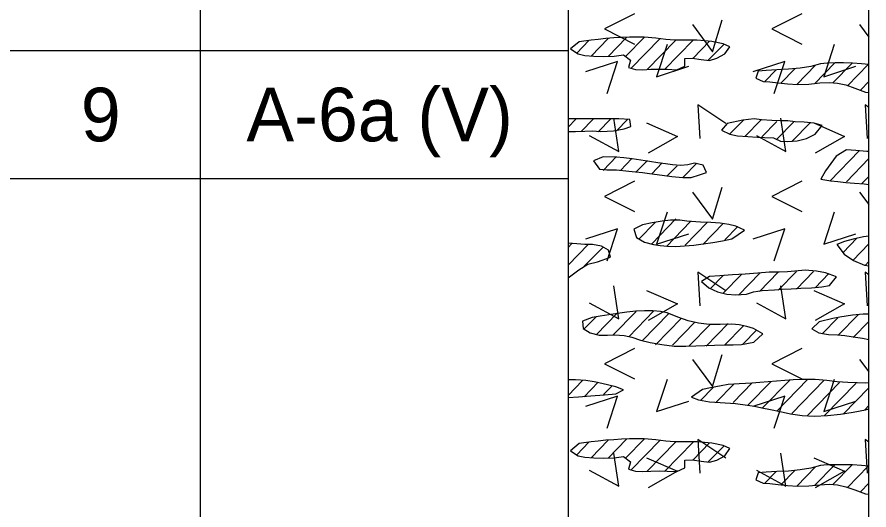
# Model space of a CAD drawing. Extents: x 0 to 0.83, y -0.65 to 1.27.
# Drawn here: x 0.7272 to 0.8333, y 0.4451 to 0.5064 of the extents above; entities that cross this region are included whole.
import ezdxf

# ---------------------------------------------------------------- set-up
doc = ezdxf.new("R2010")
doc.units = 0

msp = doc.modelspace()

# ---------------------------------------------------------------- linework, layer by layer
for points in [[(0, 0), (0.83333, 0), (0.83333, 1.275), (0, 1.275)], [(0, 0), (0.83333, 0), (0.83333, 1.275), (0, 1.275)], [(0, 0), (0.83333, 0), (0.83333, 1.275), (0, 1.275)], [(0, 0), (0.83333, 0), (0.83333, 1.275), (0, 1.275)], [(0, 0), (0.83333, 0), (0.83333, 1.275), (0, 1.275)], [(0.79708, 0.50181), (0.79794, 0.50163), (0.79904, 0.50152), (0.80028, 0.50149), (0.80156, 0.50154), (0.80274, 0.50169), (0.80361, 0.50103), (0.80338, 0.50014), (0.80422, 0.49987), (0.80517, 0.49985), (0.80613, 0.4999), (0.8072, 0.49993), (0.80818, 0.4999), (0.80939, 0.49983), (0.81037, 0.50029), (0.81038, 0.50124), (0.8113, 0.5013), (0.81244, 0.50112), (0.81346, 0.50101), (0.81438, 0.50127), (0.81539, 0.50181), (0.81601, 0.50272), (0.81517, 0.50309), (0.81374, 0.50337), (0.81285, 0.50346), (0.81187, 0.50352), (0.81, 0.50352), (0.8091, 0.50354), (0.808, 0.50362), (0.80678, 0.50377), (0.8053, 0.5039), (0.80443, 0.50392), (0.80349, 0.5039), (0.80251, 0.50386), (0.80152, 0.5038), (0.80054, 0.50372), (0.79959, 0.50363), (0.7987, 0.50353), (0.79722, 0.50331), (0.79614, 0.50243)], [(0.83241, 0.50059), (0.83129, 0.50066), (0.83017, 0.50069), (0.8291, 0.50069), (0.82811, 0.50066), (0.82728, 0.50057), (0.82608, 0.50027), (0.82476, 0.50004), (0.8233, 0.4999), (0.82183, 0.49982), (0.82051, 0.49976), (0.81951, 0.49966), (0.81922, 0.4988), (0.82013, 0.49838), (0.82097, 0.49833), (0.822, 0.49823), (0.82318, 0.4981), (0.82448, 0.49801), (0.82584, 0.49804), (0.82719, 0.4982), (0.82836, 0.49827), (0.8294, 0.49819), (0.83043, 0.49795), (0.83156, 0.49756), (0.83291, 0.49707), (0.83333, 0.497), (0.83333, 0.50052)], [(0.79583, 0.49218), (0.79676, 0.49217), (0.79792, 0.49219), (0.79882, 0.49223), (0.79992, 0.49218), (0.80151, 0.49223), (0.80282, 0.49248), (0.80367, 0.4928), (0.80354, 0.49364), (0.80216, 0.49373), (0.79583, 0.49373)], [(0.81822, 0.49153), (0.81944, 0.49147), (0.82033, 0.49143), (0.82145, 0.49137), (0.82229, 0.49095), (0.82324, 0.49091), (0.82438, 0.49101), (0.82555, 0.4913), (0.82662, 0.49181), (0.82749, 0.4929), (0.82651, 0.49321), (0.82524, 0.49331), (0.82413, 0.49337), (0.82324, 0.49348), (0.82226, 0.4935), (0.82121, 0.49352), (0.81995, 0.49361), (0.81902, 0.49373), (0.81761, 0.49359), (0.81566, 0.49314), (0.81496, 0.49231), (0.81598, 0.49182), (0.81695, 0.49164)], [(0.83305, 0.48968), (0.83171, 0.48979), (0.83054, 0.48989), (0.82925, 0.48907), (0.82857, 0.48816), (0.82792, 0.48727), (0.82735, 0.48624), (0.82858, 0.48602), (0.82945, 0.48592), (0.83045, 0.48582), (0.83155, 0.48573), (0.83272, 0.48563), (0.83333, 0.48558), (0.83333, 0.48967)], [(0.80066, 0.48738), (0.80188, 0.48737), (0.80339, 0.48724), (0.80423, 0.48715), (0.8051, 0.48704), (0.806, 0.48692), (0.80692, 0.4868), (0.80784, 0.48668), (0.80875, 0.48657), (0.81014, 0.48643), (0.81119, 0.48644), (0.81222, 0.48678), (0.81308, 0.48707), (0.81267, 0.48797), (0.8116, 0.48822), (0.81075, 0.48802), (0.80989, 0.48794), (0.80885, 0.48802), (0.80799, 0.48813), (0.80703, 0.48827), (0.806, 0.48844), (0.80492, 0.4886), (0.80384, 0.48876), (0.8028, 0.48889), (0.80182, 0.48898), (0.8002, 0.48899), (0.79901, 0.48852), (0.79974, 0.48748)], [(0.81233, 0.48087), (0.81063, 0.48099), (0.80977, 0.48112), (0.8086, 0.48113), (0.80755, 0.48099), (0.80632, 0.48079), (0.80513, 0.48054), (0.80403, 0.48002), (0.80436, 0.47896), (0.80536, 0.47839), (0.80647, 0.4781), (0.8073, 0.47795), (0.80824, 0.47787), (0.80926, 0.47786), (0.81035, 0.47791), (0.81149, 0.47801), (0.81267, 0.47816), (0.81386, 0.47835), (0.81506, 0.47856), (0.81625, 0.47879), (0.81783, 0.47987), (0.81673, 0.48037), (0.81585, 0.48057), (0.8148, 0.48073), (0.81361, 0.48083)], [(0.83265, 0.47906), (0.83136, 0.47875), (0.83028, 0.47847), (0.82934, 0.47808), (0.83026, 0.47688), (0.83142, 0.47612), (0.83279, 0.47554), (0.83333, 0.47544), (0.83333, 0.47915)], [(0.79583, 0.47396), (0.79719, 0.47495), (0.79831, 0.47565), (0.79951, 0.47592), (0.80111, 0.47653), (0.80086, 0.47741), (0.80002, 0.47789), (0.79889, 0.47808), (0.79791, 0.47811), (0.79694, 0.47817), (0.79583, 0.47825)], [(0.82537, 0.4749), (0.82408, 0.47476), (0.82319, 0.4747), (0.82214, 0.47467), (0.82091, 0.47464), (0.81947, 0.47454), (0.81792, 0.47442), (0.81632, 0.4743), (0.81475, 0.47421), (0.81348, 0.47411), (0.81247, 0.47347), (0.81337, 0.47271), (0.81444, 0.47221), (0.81561, 0.47192), (0.81675, 0.47181), (0.81807, 0.47193), (0.81896, 0.4722), (0.82003, 0.47235), (0.82157, 0.47247), (0.82253, 0.47252), (0.82362, 0.47258), (0.82483, 0.47264), (0.82618, 0.47271), (0.82745, 0.47282), (0.82842, 0.47299), (0.82927, 0.47405), (0.82791, 0.47457), (0.82679, 0.47477)], [(0.79885, 0.469), (0.79763, 0.46854), (0.79773, 0.46764), (0.79859, 0.46712), (0.7997, 0.46682), (0.80074, 0.46683), (0.80165, 0.46684), (0.80281, 0.46676), (0.80377, 0.46655), (0.80486, 0.4662), (0.80606, 0.46591), (0.80751, 0.46563), (0.80905, 0.46545), (0.81052, 0.46542), (0.81177, 0.46547), (0.81289, 0.46551), (0.81408, 0.46555), (0.81553, 0.46559), (0.81642, 0.46562), (0.81745, 0.46565), (0.81897, 0.46592), (0.82011, 0.46696), (0.81896, 0.46763), (0.8181, 0.46789), (0.81717, 0.46809), (0.81626, 0.46819), (0.81479, 0.46814), (0.81343, 0.46814), (0.8121, 0.46829), (0.8108, 0.46859), (0.80953, 0.46905), (0.8082, 0.4696), (0.80736, 0.46976), (0.8064, 0.46984), (0.80536, 0.46984), (0.80427, 0.46978), (0.80314, 0.46967), (0.80201, 0.46952), (0.8009, 0.46935), (0.79984, 0.46917)], [(0.83263, 0.46944), (0.83126, 0.4693), (0.82969, 0.46904), (0.82883, 0.46887), (0.82712, 0.46846), (0.82623, 0.46759), (0.82708, 0.4671), (0.82831, 0.46691), (0.82941, 0.46684), (0.83033, 0.46675), (0.83165, 0.46657), (0.83253, 0.46643), (0.83333, 0.46629), (0.83333, 0.46944)], [(0.79583, 0.45904), (0.79715, 0.45915), (0.79814, 0.45922), (0.79922, 0.4593), (0.80039, 0.45938), (0.80179, 0.45951), (0.80275, 0.46002), (0.80179, 0.46036), (0.80091, 0.46058), (0.80003, 0.4608), (0.79909, 0.461), (0.79803, 0.46117), (0.79677, 0.46127), (0.79583, 0.46125)], [(0.82816, 0.45679), (0.82978, 0.45696), (0.83137, 0.45721), (0.8329, 0.45752), (0.83333, 0.45763), (0.83333, 0.46087), (0.83295, 0.46084), (0.83188, 0.46086), (0.83071, 0.46091), (0.82938, 0.46101), (0.82807, 0.46118), (0.82662, 0.4613), (0.82576, 0.4613), (0.82484, 0.46128), (0.82387, 0.46123), (0.82286, 0.46116), (0.82182, 0.46108), (0.82077, 0.46099), (0.81973, 0.46091), (0.81872, 0.46084), (0.81715, 0.46074), (0.81579, 0.46065), (0.81491, 0.46052), (0.81357, 0.46024), (0.8126, 0.46003), (0.81121, 0.45911), (0.8121, 0.45875), (0.81345, 0.4585), (0.81479, 0.45841), (0.81668, 0.45831), (0.81818, 0.45811), (0.81905, 0.45796), (0.82, 0.45778), (0.82107, 0.45757), (0.82225, 0.45732), (0.82357, 0.45703), (0.82501, 0.4568), (0.82656, 0.45673)], [(0.79708, 0.45181), (0.79794, 0.45163), (0.79904, 0.45152), (0.80028, 0.45149), (0.80156, 0.45154), (0.80274, 0.45169), (0.80361, 0.45103), (0.80338, 0.45014), (0.80422, 0.44987), (0.80517, 0.44985), (0.80613, 0.4499), (0.8072, 0.44993), (0.80818, 0.4499), (0.80939, 0.44983), (0.81037, 0.45029), (0.81038, 0.45124), (0.8113, 0.4513), (0.81244, 0.45112), (0.81346, 0.45101), (0.81438, 0.45127), (0.81539, 0.45181), (0.81601, 0.45272), (0.81517, 0.45309), (0.81374, 0.45337), (0.81285, 0.45346), (0.81187, 0.45352), (0.81, 0.45352), (0.8091, 0.45354), (0.808, 0.45362), (0.80678, 0.45377), (0.8053, 0.4539), (0.80443, 0.45392), (0.80349, 0.4539), (0.80251, 0.45386), (0.80152, 0.4538), (0.80054, 0.45372), (0.79959, 0.45363), (0.7987, 0.45353), (0.79722, 0.45331), (0.79614, 0.45243)], [(0.83241, 0.45059), (0.83129, 0.45066), (0.83017, 0.45069), (0.8291, 0.45069), (0.82811, 0.45066), (0.82728, 0.45057), (0.82608, 0.45027), (0.82476, 0.45004), (0.8233, 0.4499), (0.82183, 0.44982), (0.82051, 0.44976), (0.81951, 0.44966), (0.81922, 0.4488), (0.82013, 0.44838), (0.82097, 0.44833), (0.822, 0.44823), (0.82318, 0.4481), (0.82448, 0.44801), (0.82584, 0.44804), (0.82719, 0.4482), (0.82836, 0.44827), (0.8294, 0.44819), (0.83043, 0.44795), (0.83156, 0.44756), (0.83291, 0.44707), (0.83333, 0.447), (0.83333, 0.45052)]]:
    msp.add_lwpolyline(points, close=True)
for points in [[(0.75, 1.22083), (0.75, -0.64575)], [(0.75, 1.22083), (0.75, -0.64575)], [(0.79583, 1.22083), (0.79583, -0.64575)], [(0.83333, -0.64575), (0.83333, 1.13365)], [(0.80412, 0.5068), (0.80038, 0.50492), (0.80412, 0.50305)], [(0.82496, 0.5068), (0.82121, 0.50492), (0.82496, 0.50305)], [(0.81134, 0.50546), (0.81384, 0.50208), (0.81503, 0.50608)], [(0.83217, 0.50546), (0.83333, 0.50389)], [(0.79844, 0.50349), (0.79691, 0.50192)], [(0.79871, 0.50155), (0.80085, 0.50374)], [(0.80083, 0.50151), (0.80311, 0.50385)], [(0.80534, 0.50392), (0.80299, 0.50151)], [(0.80367, 0.5), (0.80732, 0.50374)], [(0.80571, 0.49988), (0.80924, 0.50349)], [(0.81142, 0.50351), (0.80785, 0.49986)], [(0.81141, 0.50129), (0.81348, 0.50341)], [(0.725, 0.50225), (0.75, 0.50225)], [(0.75, 0.50225), (0.79583, 0.50225)], [(0.80818, 0.50297), (0.80687, 0.49897), (0.81087, 0.50028)], [(0.81528, 0.50304), (0.81331, 0.50103)], [(0.82901, 0.50297), (0.8277, 0.49897), (0.8317, 0.50028)], [(0.80069, 0.49689), (0.802, 0.50089), (0.798, 0.49957)], [(0.82152, 0.49689), (0.82284, 0.50089), (0.81884, 0.49957)], [(0.82433, 0.49802), (0.82666, 0.50041)], [(0.82909, 0.50069), (0.82656, 0.4981)], [(0.82885, 0.49823), (0.83122, 0.50066)], [(0.83325, 0.50052), (0.83065, 0.49786)], [(0.82035, 0.49837), (0.82176, 0.49982)], [(0.82233, 0.49819), (0.82408, 0.49998)], [(0.83333, 0.4984), (0.83227, 0.49731)], [(0.81551, 0.49316), (0.81201, 0.49547), (0.81226, 0.49128)], [(0.83333, 0.49515), (0.83284, 0.49547), (0.83309, 0.49128)], [(0.79583, 0.4927), (0.79681, 0.4937)], [(0.79898, 0.49371), (0.79747, 0.49217)], [(0.79847, 0.49168), (0.80215, 0.48968), (0.80153, 0.4938)], [(0.80116, 0.49373), (0.79959, 0.49213)], [(0.80328, 0.49369), (0.80188, 0.49226)], [(0.8193, 0.49168), (0.82299, 0.48968), (0.82236, 0.4938)], [(0.80562, 0.49322), (0.80946, 0.49154), (0.80581, 0.48948)], [(0.8177, 0.49359), (0.81596, 0.49181)], [(0.81988, 0.49361), (0.81785, 0.49153)], [(0.82185, 0.49342), (0.81997, 0.49149)], [(0.824, 0.49341), (0.82178, 0.49113)], [(0.82601, 0.49325), (0.82378, 0.49097)], [(0.82645, 0.49322), (0.83029, 0.49154), (0.82664, 0.48948)], [(0.83217, 0.4898), (0.82844, 0.48599)], [(0.80188, 0.48903), (0.8002, 0.48731)], [(0.8038, 0.48879), (0.80237, 0.48732)], [(0.80575, 0.48857), (0.80429, 0.48708)], [(0.83333, 0.48879), (0.83052, 0.48591)], [(0.80758, 0.48824), (0.80627, 0.48689)], [(0.80941, 0.4879), (0.80816, 0.48662)], [(0.81188, 0.48821), (0.81016, 0.48646)], [(0.725, 0.4863), (0.75, 0.4863)], [(0.75, 0.4863), (0.79583, 0.4863)], [(0.83333, 0.48657), (0.83245, 0.48567)], [(0.80412, 0.48596), (0.80038, 0.48409), (0.80412, 0.48221)], [(0.81134, 0.48462), (0.81384, 0.48125), (0.81503, 0.48525)], [(0.82496, 0.48596), (0.82121, 0.48409), (0.82496, 0.48221)], [(0.83217, 0.48462), (0.83333, 0.48306)], [(0.80818, 0.48213), (0.80687, 0.47813), (0.81087, 0.47944)], [(0.82901, 0.48213), (0.8277, 0.47813), (0.8317, 0.47944)], [(0.80626, 0.47819), (0.80928, 0.48128)], [(0.80809, 0.47785), (0.81111, 0.48095)], [(0.80069, 0.47605), (0.802, 0.48005), (0.798, 0.47874)], [(0.80465, 0.47875), (0.80667, 0.48083)], [(0.81041, 0.47802), (0.81318, 0.48085)], [(0.81264, 0.47809), (0.81518, 0.48069)], [(0.81536, 0.47867), (0.81699, 0.48033)], [(0.82152, 0.47605), (0.82284, 0.48005), (0.81884, 0.47874)], [(0.8301, 0.47709), (0.83184, 0.47887)], [(0.7963, 0.47821), (0.79583, 0.47772)], [(0.79834, 0.47808), (0.79583, 0.47551)], [(0.79786, 0.47538), (0.80023, 0.47781)], [(0.83131, 0.47612), (0.83333, 0.47819)], [(0.83285, 0.47549), (0.83333, 0.47598)], [(0.81551, 0.47233), (0.81201, 0.47464), (0.81226, 0.47045)], [(0.8197, 0.47225), (0.82203, 0.47465)], [(0.82202, 0.47241), (0.8243, 0.47475)], [(0.82431, 0.47255), (0.82644, 0.47474)], [(0.83333, 0.47432), (0.83284, 0.47464), (0.83309, 0.47045)], [(0.81519, 0.47428), (0.81354, 0.47258)], [(0.81514, 0.47201), (0.81748, 0.47441)], [(0.81709, 0.4718), (0.81974, 0.47451)], [(0.82663, 0.47271), (0.82834, 0.47447)], [(0.79847, 0.47084), (0.80215, 0.46884), (0.80153, 0.47297)], [(0.8193, 0.47084), (0.82299, 0.46884), (0.82236, 0.47297)], [(0.80562, 0.47239), (0.80946, 0.47071), (0.80581, 0.46864)], [(0.82645, 0.47239), (0.83029, 0.47071), (0.82664, 0.46864)], [(0.79933, 0.46687), (0.80195, 0.46956)], [(0.80142, 0.4668), (0.8043, 0.46975)], [(0.80653, 0.46983), (0.8034, 0.46661)], [(0.80506, 0.4661), (0.8084, 0.46952)], [(0.83203, 0.46939), (0.82949, 0.46679)], [(0.79938, 0.46913), (0.79786, 0.46758)], [(0.80997, 0.46893), (0.80675, 0.46562)], [(0.81164, 0.46842), (0.80884, 0.46556)], [(0.81303, 0.46542), (0.81579, 0.46825)], [(0.82751, 0.46698), (0.82945, 0.46896)], [(0.83138, 0.46652), (0.83333, 0.46852)], [(0.81353, 0.46814), (0.81094, 0.46549)], [(0.81534, 0.46558), (0.81768, 0.46797)], [(0.8176, 0.46568), (0.81934, 0.46747)], [(0.83333, 0.4663), (0.83333, 0.4663)], [(0.80412, 0.46513), (0.80038, 0.46326), (0.80412, 0.46138)], [(0.82496, 0.46513), (0.82121, 0.46326), (0.82496, 0.46138)], [(0.81134, 0.46379), (0.81384, 0.46041), (0.81503, 0.46441)], [(0.83217, 0.46379), (0.83333, 0.46223)], [(0.79765, 0.46115), (0.79583, 0.45928)], [(0.7996, 0.46094), (0.79786, 0.45915)], [(0.80818, 0.4613), (0.80687, 0.4573), (0.81087, 0.45861)], [(0.8164, 0.45841), (0.81879, 0.46086)], [(0.81829, 0.45813), (0.82114, 0.46105)], [(0.82004, 0.45771), (0.82346, 0.46122)], [(0.82569, 0.46129), (0.82184, 0.45735)], [(0.82775, 0.46119), (0.8237, 0.45704)], [(0.82964, 0.46092), (0.82557, 0.45674)], [(0.82901, 0.4613), (0.8277, 0.4573), (0.8317, 0.45861)], [(0.83173, 0.46085), (0.82774, 0.45676)], [(0.8013, 0.46046), (0.80027, 0.45941)], [(0.81392, 0.4603), (0.81235, 0.45869)], [(0.8143, 0.45848), (0.8165, 0.46073)], [(0.83333, 0.46027), (0.83012, 0.45698)], [(0.80069, 0.45522), (0.802, 0.45922), (0.798, 0.45791)], [(0.82152, 0.45522), (0.82284, 0.45922), (0.81884, 0.45791)], [(0.83281, 0.45752), (0.83333, 0.45806)], [(0.79844, 0.45349), (0.79691, 0.45192)], [(0.79871, 0.45155), (0.80085, 0.45374)], [(0.80083, 0.45151), (0.80311, 0.45385)], [(0.80534, 0.45392), (0.80299, 0.45151)], [(0.80367, 0.45), (0.80732, 0.45374)], [(0.80571, 0.44988), (0.80924, 0.45349)], [(0.81142, 0.45351), (0.80785, 0.44986)], [(0.81141, 0.45129), (0.81348, 0.45341)], [(0.81551, 0.45149), (0.81201, 0.45381), (0.81226, 0.44962)], [(0.83333, 0.45348), (0.83284, 0.45381), (0.83309, 0.44962)], [(0.81528, 0.45304), (0.81331, 0.45103)], [(0.79847, 0.45001), (0.80215, 0.44801), (0.80153, 0.45214)], [(0.80562, 0.45156), (0.80946, 0.44987), (0.80581, 0.44781)], [(0.8193, 0.45001), (0.82299, 0.44801), (0.82236, 0.45214)], [(0.82645, 0.45156), (0.83029, 0.44987), (0.82664, 0.44781)], [(0.82433, 0.44802), (0.82666, 0.45041)], [(0.82909, 0.45069), (0.82656, 0.4481)], [(0.82885, 0.44823), (0.83122, 0.45066)], [(0.83325, 0.45052), (0.83065, 0.44786)], [(0.82035, 0.44837), (0.82176, 0.44982)], [(0.82233, 0.44819), (0.82408, 0.44998)], [(0.83333, 0.4484), (0.83227, 0.44731)]]:
    msp.add_lwpolyline(points)

# ---------------------------------------------------------------- texts
for s, height, p in [('A-6a (V)', 0.006667, (0.75575, 0.49094)), ('9', 0.00667, (0.73512, 0.49094))]:
    msp.add_text(s, height=height).set_placement(p)

doc.saveas('drawing.dxf')
